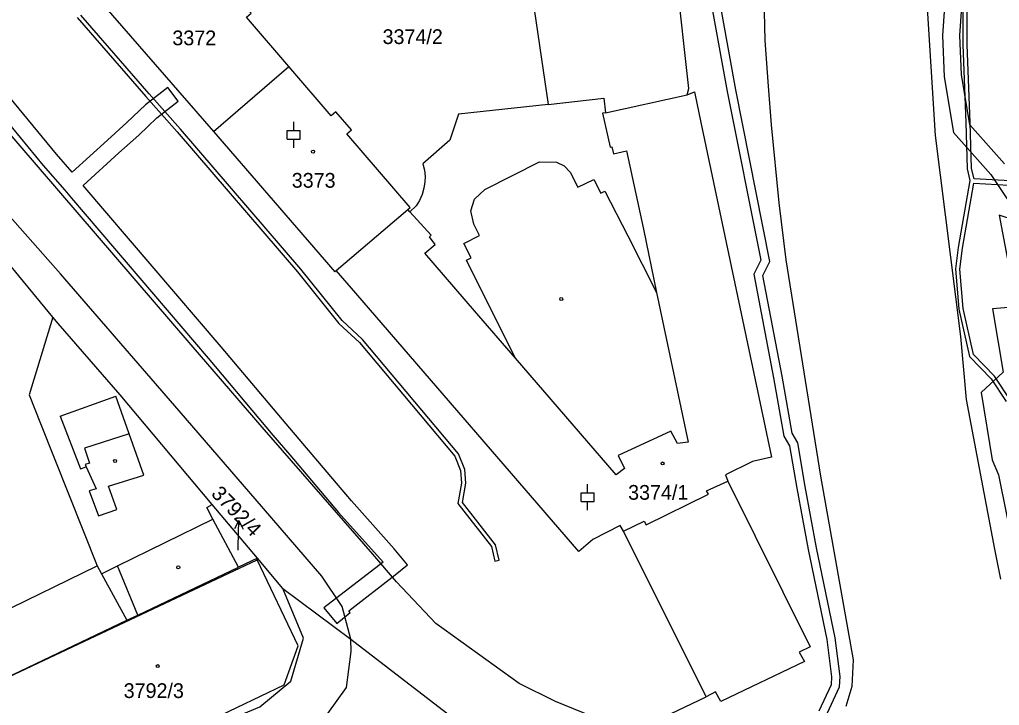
# Model space of a CAD drawing. Extents: x -756746 to -753363, y -1166406 to -1161727.
# Drawn here: x -756022.3 to -755909.2, y -1165463.3 to -1165384.2 of the extents above; entities that cross this region are included whole.
import ezdxf

# ---------------------------------------------------------------- set-up
doc = ezdxf.new("R2010")
doc.units = 0
for name, color, linetype in [('Hranice parcel', 7, 'Continuous'), ('Parcelní čísla', 7, 'Continuous'), ('Pop  PČ popisy', 7, 'Continuous'), ('Vnitřní kresba', 7, 'Continuous'), ('Věcná břemena k části', 7, 'Continuous'), ('Značky budov', 7, 'Continuous'), ('Značky kultur', 7, 'Continuous')]:
    doc.layers.add(name, color=color, linetype=linetype)

msp = doc.modelspace()

# ---------------------------------------------------------------- linework, layer by layer
at = {"layer": 'Hranice parcel'}
for p, q in [((-756013.93, -1165380.94), (-755999.91, -1165397.1)), ((-755999.91, -1165397.1), (-755991.2, -1165389.59)), ((-755985.72, -1165413.15), (-755977.47, -1165406.1)), ((-755994.83, -1165446.33), (-756000.04, -1165440.13)), ((-755994.83, -1165446.33), (-755997, -1165447.36)), ((-755991.88, -1165449.84), (-755994.83, -1165446.33))]:
    msp.add_line(p, q, dxfattribs=at)
for points in [[(-755945.21, -1165392.87), (-755945.04, -1165392.15), (-755946.45, -1165379.25), (-755935.77, -1165320.67), (-755935.43, -1165318.22)], [(-755991.2, -1165389.59), (-755996.09, -1165383.9), (-755995.55, -1165383.44), (-755997.35, -1165381.35), (-755997.89, -1165381.82), (-756005.24, -1165373.27), (-756005.81, -1165372.62)], [(-755966.41, -1165374.3), (-755964.08, -1165374.82), (-755961.26, -1165393.97)], [(-755977.47, -1165406.1), (-755977.19, -1165405.86), (-755984.51, -1165397.36), (-755983.97, -1165396.89), (-755985.77, -1165394.81), (-755986.31, -1165395.27), (-755991.2, -1165389.59)], [(-755961.26, -1165393.97), (-755954.84, -1165393.24), (-755954.65, -1165394.93), (-755945.21, -1165392.87)], [(-755945.21, -1165392.87), (-755944.38, -1165392.52), (-755944.33, -1165392.71), (-755943.63, -1165396.06), (-755935.48, -1165434.69), (-755937.68, -1165435.16), (-755940.81, -1165436.7), (-755940.52, -1165437.45), (-755931.02, -1165456.57), (-755932.29, -1165457.17), (-755931.67, -1165458.24), (-755941.33, -1165462.89), (-755941.95, -1165461.77), (-755943.04, -1165462.33)], [(-755961.26, -1165393.97), (-755971.63, -1165395.09), (-755972.62, -1165398.08), (-755975.72, -1165400.83)], [(-755999.91, -1165397.1), (-755985.88, -1165413.29), (-755985.72, -1165413.15)], [(-755975.72, -1165400.83), (-755975.55, -1165401.55), (-755975.48, -1165402.29), (-755975.5, -1165402.91), (-755975.61, -1165403.65), (-755975.82, -1165404.36), (-755976.13, -1165405.04), (-755976.52, -1165405.67)], [(-755976.52, -1165405.67), (-755977.22, -1165406.38), (-755977.47, -1165406.1)], [(-755900.61, -1165409.55), (-755909.21, -1165406.74), (-755906.77, -1165419.78)], [(-756000.04, -1165440.13), (-756010.67, -1165427.48), (-756017.81, -1165419.27), (-756018.44, -1165418.51), (-756024.72, -1165410.96)], [(-755943.04, -1165462.33), (-755952.58, -1165443.21), (-755952.94, -1165442.55), (-755956.13, -1165444.16), (-755957.72, -1165445.58), (-755983.47, -1165415.76), (-755985.72, -1165413.15)], [(-755997, -1165447.36), (-755999.95, -1165441.84), (-756000.67, -1165440.47), (-756000.04, -1165440.13)], [(-756013.6, -1165471.4), (-755991.72, -1165460.93), (-755990.11, -1165456.43), (-755994.86, -1165446.52), (-755994.83, -1165446.33)], [(-756027.01, -1165461.65), (-756021.32, -1165458.94), (-756009.88, -1165453.49), (-756008.61, -1165452.89), (-755997, -1165447.36)], [(-756013.6, -1165471.4), (-755994.54, -1165463.47), (-755990.97, -1165460.51), (-755989.51, -1165455.55), (-755991.88, -1165449.84)], [(-755991.88, -1165449.84), (-755984.06, -1165455.67), (-755966.66, -1165469.06), (-755963.17, -1165471.87)], [(-755963.17, -1165471.87), (-755959.68, -1165470.22), (-755951.2, -1165466.2), (-755943.04, -1165462.33)]]:
    msp.add_lwpolyline(points, dxfattribs=at)
at = {"layer": 'Pop  PČ popisy'}
for p, q in [((-755996.95, -1165441.98), (-755997.48, -1165442.96)), ((-755997.05, -1165444.98), (-755996.95, -1165441.98)), ((-755996.95, -1165441.98), (-755996.48, -1165443)), ((-755997.06, -1165445.42), (-755997.05, -1165444.98))]:
    msp.add_line(p, q, dxfattribs=at)
at = {"layer": 'Vnitřní kresba'}
for p, q in [((-755936.45, -1165378.58), (-755936.27, -1165386.61)), ((-755916.56, -1165397.54), (-755917.72, -1165379.37)), ((-755936.27, -1165386.61), (-755935.87, -1165391.87)), ((-755935.87, -1165391.87), (-755935.53, -1165396.33)), ((-755954.65, -1165394.93), (-755954.99, -1165394.96)), ((-755954.99, -1165394.96), (-755954.12, -1165398.89)), ((-756002.45, -1165421.71), (-756024.31, -1165396.3)), ((-755935.53, -1165396.33), (-755934.63, -1165405.34)), ((-755913.65, -1165420.76), (-755916.56, -1165397.54)), ((-756030.23, -1165399.19), (-756017.55, -1165413.52)), ((-755954.12, -1165398.89), (-755953.93, -1165398.85)), ((-755953.93, -1165398.85), (-755953.74, -1165399.66)), ((-755953.74, -1165399.66), (-755952.21, -1165399.33)), ((-755952.21, -1165399.33), (-755950.27, -1165408.36)), ((-755968.59, -1165403.8), (-755962.25, -1165400.61)), ((-755962.25, -1165400.61), (-755960.32, -1165400.65)), ((-755960.32, -1165400.65), (-755959.43, -1165401.04)), ((-755959.43, -1165401.04), (-755958.73, -1165401.78)), ((-755958.73, -1165401.78), (-755957.83, -1165403.53)), ((-755957.83, -1165403.53), (-755955.98, -1165402.64)), ((-755955.98, -1165402.64), (-755955.17, -1165404.21)), ((-755969.77, -1165404.89), (-755968.59, -1165403.8)), ((-755970.2, -1165406.24), (-755969.77, -1165404.89)), ((-755955.17, -1165404.21), (-755954.72, -1165403.97)), ((-755954.72, -1165403.97), (-755952.08, -1165409.14)), ((-755934.63, -1165405.34), (-755933.83, -1165411.9)), ((-755969.84, -1165407.77), (-755970.2, -1165406.24)), ((-755969.18, -1165409.11), (-755969.84, -1165407.77)), ((-755971, -1165410.03), (-755969.18, -1165409.11)), ((-755952.08, -1165409.14), (-755948.76, -1165415.66)), ((-755950.27, -1165408.36), (-755948.76, -1165415.66)), ((-755970.16, -1165411.68), (-755971, -1165410.03)), ((-755970.69, -1165411.95), (-755970.16, -1165411.68)), ((-755968.1, -1165417.12), (-755970.69, -1165411.95)), ((-755933.83, -1165411.9), (-755929.83, -1165436.85)), ((-756004.37, -1165428.76), (-756017.55, -1165413.52)), ((-755948.76, -1165415.66), (-755945.1, -1165432.94)), ((-755965.02, -1165423.27), (-755968.1, -1165417.12)), ((-756018.44, -1165418.51), (-756021.16, -1165427.49)), ((-755913, -1165428.04), (-755913.65, -1165420.76)), ((-755994.28, -1165431.22), (-756002.45, -1165421.71)), ((-755953.42, -1165436.71), (-755965.02, -1165423.27)), ((-756021.16, -1165427.49), (-756019.85, -1165430.78)), ((-756017.59, -1165429.96), (-756011.16, -1165427.63)), ((-756009.63, -1165432), (-756011.16, -1165427.63)), ((-755909.7, -1165445.3), (-755913, -1165428.04)), ((-755995.09, -1165439.48), (-756004.37, -1165428.76)), ((-756019.85, -1165430.78), (-756013.3, -1165447.23)), ((-756017.59, -1165429.96), (-756015.24, -1165436.01)), ((-756009.63, -1165432), (-756014.77, -1165433.64)), ((-756007.95, -1165436.76), (-756009.63, -1165432)), ((-755981.51, -1165445.86), (-755994.28, -1165431.22)), ((-755947.12, -1165431.66), (-755953.18, -1165434.49)), ((-755946.35, -1165433.08), (-755947.12, -1165431.66)), ((-755945.1, -1165432.94), (-755946.35, -1165433.08)), ((-756014.77, -1165433.64), (-756014.22, -1165435.36)), ((-756014.22, -1165435.36), (-756014.7, -1165435.52)), ((-755953.18, -1165434.49), (-755952.47, -1165436)), ((-756015.24, -1165436.01), (-756014.6, -1165435.8)), ((-756014.7, -1165435.52), (-756014.6, -1165435.8)), ((-756014.6, -1165435.8), (-756013.45, -1165438.32)), ((-755952.47, -1165436), (-755953.42, -1165436.71)), ((-756012.01, -1165438.03), (-756007.95, -1165436.76)), ((-755942.98, -1165438.58), (-755940.52, -1165437.45)), ((-755929.83, -1165436.85), (-755926.05, -1165458.08)), ((-756013.45, -1165438.32), (-756014.23, -1165438.55)), ((-756014.23, -1165438.55), (-756013.15, -1165441.43)), ((-756011.03, -1165440.7), (-756012.01, -1165438.03)), ((-755942.78, -1165438.96), (-755942.98, -1165438.58)), ((-755987.38, -1165448.41), (-755995.09, -1165439.48)), ((-755949.96, -1165442.48), (-755942.78, -1165438.96)), ((-756013.15, -1165441.43), (-756011.03, -1165440.7)), ((-756010.97, -1165447.23), (-755999.95, -1165441.84)), ((-755952.58, -1165443.21), (-755950.17, -1165442.08)), ((-755950.17, -1165442.08), (-755949.96, -1165442.48)), ((-755909.03, -1165448.76), (-755909.7, -1165445.3)), ((-756027.01, -1165461.65), (-755994.86, -1165446.52)), ((-755978.78, -1165449.05), (-755981.51, -1165445.86)), ((-756045.12, -1165462.64), (-756013.3, -1165447.23)), ((-756013.3, -1165447.23), (-756012.81, -1165448.13)), ((-756012.81, -1165448.13), (-756010.97, -1165447.23)), ((-756008.61, -1165452.89), (-756010.97, -1165447.23)), ((-756012.81, -1165448.13), (-756009.88, -1165453.49)), ((-755985.06, -1165451.91), (-755987.38, -1165448.41)), ((-755974.24, -1165453.88), (-755978.78, -1165449.05)), ((-755984.06, -1165455.67), (-755985.06, -1165451.91)), ((-755964.62, -1165460.79), (-755974.24, -1165453.88)), ((-755984.02, -1165457.09), (-755984.06, -1165455.67)), ((-755984.56, -1165461.24), (-755984.02, -1165457.09)), ((-755926.05, -1165458.08), (-755926.24, -1165461.16)), ((-755987.78, -1165465.75), (-755984.56, -1165461.24)), ((-755960.41, -1165462.89), (-755964.62, -1165460.79)), ((-755926.24, -1165461.16), (-755926.93, -1165463.43)), ((-755956.28, -1165464.57), (-755960.41, -1165462.89))]:
    msp.add_line(p, q, dxfattribs=at)
msp.add_lwpolyline([(-755965.02, -1165423.27), (-755969.76, -1165417.78), (-755975.49, -1165411.14), (-755974.31, -1165410.12), (-755974.98, -1165409.25), (-755974.76, -1165409.05), (-755977.22, -1165406.38)], dxfattribs=at)
at = {"layer": 'Věcná břemena k části'}
for points in [[(-755904.69, -1165282.58), (-755912.69, -1165341.87), (-755915.77, -1165386.03), (-755915.58, -1165390.77), (-755914.48, -1165397.21), (-755910.19, -1165402.05), (-755906.44, -1165407.65)], [(-755908.6, -1165400.83), (-755912.6, -1165396.32), (-755913.58, -1165390.5), (-755913.76, -1165386.02), (-755910.69, -1165341.97), (-755902.71, -1165282.91)], [(-755929.26, -1165464.67), (-755927.63, -1165461.19), (-755927.57, -1165459.97), (-755928.13, -1165455.54), (-755930.28, -1165445.15), (-755931.59, -1165438.07), (-755932.44, -1165433.01), (-755933.12, -1165431.9), (-755934.27, -1165425.33), (-755936.5, -1165413.71), (-755935.7, -1165412.09), (-755939.61, -1165392.3), (-755941.96, -1165379.3), (-755940.56, -1165370.61), (-755938.49, -1165358.83), (-755936.29, -1165346), (-755934.87, -1165337.55), (-755933.21, -1165326.29), (-755932.01, -1165319.14), (-755932.04, -1165317.5), (-755932.23, -1165317.07), (-755932.45, -1165316.57), (-755930.14, -1165303.5)], [(-755906.32, -1165307.9), (-755911.33, -1165343.45), (-755913.41, -1165371.71), (-755913.41, -1165387.08), (-755913.07, -1165396.06), (-755912.9, -1165401.41), (-755912.59, -1165402.76), (-755913.93, -1165410.48), (-755914.24, -1165412.96), (-755913.87, -1165417.61), (-755912.65, -1165423.06), (-755910.15, -1165425.63), (-755908.41, -1165428.25)], [(-755907.95, -1165402.78), (-755912.12, -1165402.56), (-755912.4, -1165401.35), (-755912.57, -1165396.04), (-755912.91, -1165387.08), (-755912.91, -1165371.73), (-755910.83, -1165343.51), (-755905.82, -1165307.98)], [(-755942.98, -1165379.32), (-755940.59, -1165392.48), (-755936.74, -1165411.95), (-755937.54, -1165413.57), (-755935.25, -1165425.51), (-755934.08, -1165432.26), (-755933.4, -1165433.37), (-755932.57, -1165438.25), (-755931.26, -1165445.35), (-755929.11, -1165455.7), (-755928.57, -1165460.01), (-755928.61, -1165460.95), (-755930.04, -1165463.97)], [(-756015.62, -1165383.94), (-756007.69, -1165393.07), (-756004.08, -1165397.15), (-755990.19, -1165413.3), (-755985.42, -1165419.24), (-755983.04, -1165421.44), (-755972.04, -1165434.55), (-755971.38, -1165436.21), (-755971.26, -1165437.67), (-755971.69, -1165440.04), (-755967.79, -1165445), (-755967.41, -1165446.66), (-755966.92, -1165446.55), (-755967.33, -1165444.78), (-755971.15, -1165439.9), (-755970.76, -1165437.69), (-755970.88, -1165436.09), (-755971.6, -1165434.29), (-755982.68, -1165421.1), (-755985.06, -1165418.9), (-755989.81, -1165412.98), (-756003.7, -1165396.83), (-756007.31, -1165392.75), (-756015.2, -1165383.67)], [(-756026.68, -1165392.39), (-756019.53, -1165401.01), (-756017.06, -1165403.88), (-756016.29, -1165404.8), (-756000.51, -1165423.24), (-755993.03, -1165432.12), (-755991.09, -1165434.41), (-755985.46, -1165441.05), (-755980.32, -1165446.81), (-755987.14, -1165452.07), (-755985.65, -1165453.87), (-755984.11, -1165452.59), (-755984.28, -1165452.39), (-755978.91, -1165448.25), (-755977.49, -1165447.1), (-755979.03, -1165445.25), (-755983.96, -1165439.73), (-755989.57, -1165433.11), (-755991.51, -1165430.82), (-755998.99, -1165421.94), (-756014.92, -1165403.33), (-756010.8, -1165399.57), (-756008.52, -1165397.52), (-756006.44, -1165395.53), (-756003.95, -1165393.61), (-756005.17, -1165392.03), (-756007.74, -1165394.01), (-756009.88, -1165396.06), (-756012.14, -1165398.09), (-756016.21, -1165401.8), (-756018.01, -1165399.71), (-756025.06, -1165391.21)], [(-755907.93, -1165428.07), (-755909.75, -1165425.31), (-755912.19, -1165422.82), (-755913.37, -1165417.53), (-755913.74, -1165412.98), (-755913.43, -1165410.56), (-755912.13, -1165403.06), (-755908.09, -1165403.28)], [(-755907.23, -1165417.32), (-755909.98, -1165417.54), (-755908.75, -1165424.88), (-755911.3, -1165427.22), (-755910.02, -1165434.99), (-755909.28, -1165436.72), (-755906.6, -1165450.06)]]:
    msp.add_lwpolyline(points, dxfattribs=at)
at = {"layer": 'Značky budov'}
for centre in [(-755988.4, -1165399.42), (-755959.76, -1165416.43), (-756011.25, -1165435.11), (-755948.07, -1165435.4), (-756003.95, -1165447.39), (-756006.32, -1165458.79)]:
    msp.add_circle(centre, 0.175, dxfattribs=at)
at = {"layer": 'Značky kultur'}
for p, q in [((-755991.37, -1165396.97), (-755989.87, -1165396.97)), ((-755991.37, -1165397.97), (-755991.37, -1165396.97)), ((-755990.62, -1165396.97), (-755990.62, -1165395.97)), ((-755989.87, -1165397.97), (-755989.87, -1165396.97)), ((-755991.37, -1165397.97), (-755989.87, -1165397.97)), ((-755990.62, -1165398.97), (-755990.62, -1165397.97)), ((-755957.47, -1165438.81), (-755955.97, -1165438.81)), ((-755957.47, -1165439.81), (-755957.47, -1165438.81)), ((-755956.72, -1165438.81), (-755956.72, -1165437.81)), ((-755955.97, -1165439.81), (-755955.97, -1165438.81)), ((-755957.47, -1165439.81), (-755955.97, -1165439.81)), ((-755956.72, -1165440.81), (-755956.72, -1165439.81))]:
    msp.add_line(p, q, dxfattribs=at)

# ---------------------------------------------------------------- texts
at = {"layer": 'Parcelní čísla'}
for s, p in [('3372', (-756004.64, -1165387.14)), ('3374/2', (-755980.38, -1165387)), ('3373', (-755990.86, -1165403.58)), ('3374/1', (-755952.04, -1165439.59)), ('3792/3', (-756010.26, -1165462.47))]:
    msp.add_text(s, height=1.7, dxfattribs=at).set_placement(p)
msp.add_text('3792/4', height=1.7, rotation=314, dxfattribs=at).set_placement((-756000.26, -1165438.99))

doc.saveas('drawing.dxf')
